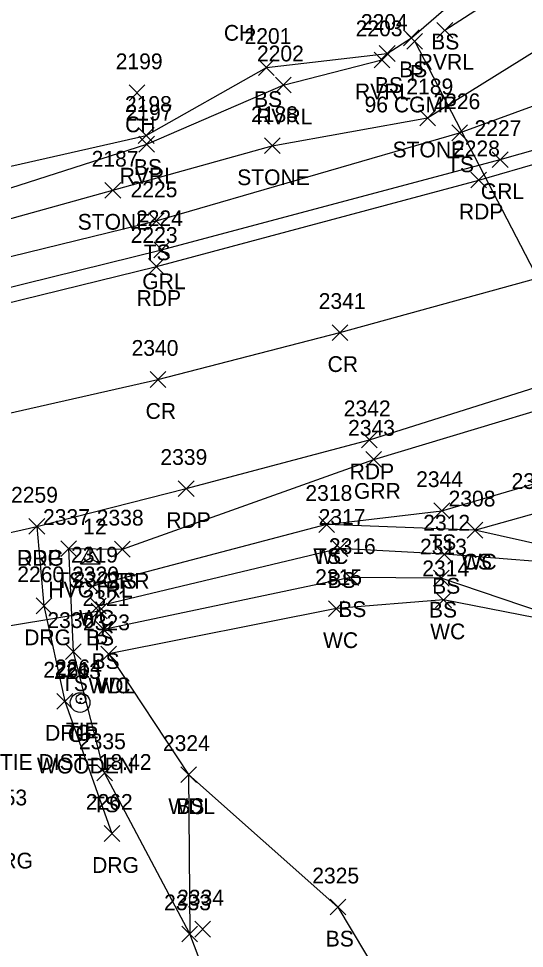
# Model space of a CAD drawing. Extents: x 1699408 to 1700423, y 840176 to 841410.
# Drawn here: x 1699855.8 to 1699920, y 840264.9 to 840382.8 of the extents above; entities that cross this region are included whole.
import ezdxf

# ---------------------------------------------------------------- set-up
doc = ezdxf.new("R2010")
doc.units = 0
for name, color, linetype in [('C_A', 7, 'Continuous'), ('C_C', 7, 'Continuous'), ('C_I', 7, 'Continuous'), ('CBP', 7, 'Continuous'), ('CPSM', 7, 'Continuous'), ('D_A', 7, 'Continuous'), ('D_C', 7, 'Continuous'), ('D_I', 7, 'Continuous'), ('D_TIC', 7, 'Continuous'), ('DCP', 7, 'Continuous'), ('L_A', 7, 'Continuous'), ('L_I', 7, 'Continuous'), ('L_TIC', 7, 'Continuous'), ('LASF', 7, 'Continuous'), ('LAWA', 7, 'Continuous'), ('LAWE', 7, 'Continuous'), ('LELB', 7, 'Continuous'), ('P_A', 7, 'Continuous'), ('P_I', 7, 'Continuous'), ('P_TIC', 7, 'Continuous'), ('PET', 7, 'Continuous'), ('PRC', 7, 'Continuous'), ('R_A', 7, 'Continuous'), ('R_C', 7, 'Continuous'), ('R_I', 7, 'Continuous'), ('R_TIC', 7, 'Continuous'), ('RDG', 7, 'Continuous'), ('RGP', 7, 'Continuous'), ('RGR', 7, 'Continuous')]:
    doc.layers.add(name, color=color, linetype=linetype)

msp = doc.modelspace()

# ---------------------------------------------------------------- linework, layer by layer
at = {"layer": 'CBP'}
for radius in [0.625, 0.0833]:
    msp.add_circle((1699863.73, 840296.5), radius, dxfattribs=at)
at = {"layer": 'CPSM'}
for p, q in [((1699863.65, 840313.64), (1699864.9, 840315.8)), ((1699866.15, 840313.64), (1699864.9, 840315.8)), ((1699864.9, 840314.36), (1699864.9, 840315.8)), ((1699863.65, 840313.64), (1699864.9, 840314.36)), ((1699864.9, 840314.36), (1699864.9, 840314.36)), ((1699864.9, 840314.36), (1699866.15, 840313.64)), ((1699863.65, 840313.64), (1699866.15, 840313.64))]:
    msp.add_line(p, q, dxfattribs=at)
at = {"layer": 'D_TIC'}
for points in [[(1699905.1, 840378.9), (1699907.1, 840380.9)], [(1699907.1, 840378.9), (1699905.1, 840380.9)], [(1699865.03, 840306.66), (1699867.03, 840308.66)], [(1699867.03, 840306.66), (1699865.03, 840308.66)]]:
    msp.add_lwpolyline(points, dxfattribs=at)
at = {"layer": 'DCP'}
for points in [[(1699906.1, 840379.9), (1699937.64, 840319.19)], [(1699838.09, 840303.05), (1699866.03, 840307.66)]]:
    msp.add_lwpolyline(points, dxfattribs=at)
at = {"layer": 'L_TIC'}
for points in [[(1699908.92, 840380.31), (1699910.92, 840382.31)], [(1699910.92, 840380.31), (1699908.92, 840382.31)], [(1699904.68, 840379.36), (1699906.68, 840381.36)], [(1699906.68, 840379.36), (1699904.68, 840381.36)], [(1699901.6, 840377.37), (1699903.6, 840379.37)], [(1699903.6, 840377.37), (1699901.6, 840379.37)], [(1699886.26, 840375.59), (1699888.26, 840377.59)], [(1699888.26, 840375.59), (1699886.26, 840377.59)], [(1699900.94, 840376.56), (1699902.94, 840378.56)], [(1699902.94, 840376.56), (1699900.94, 840378.56)], [(1699888.41, 840373.37), (1699890.41, 840375.37)], [(1699890.41, 840373.37), (1699888.41, 840375.37)], [(1699869.84, 840372.38), (1699871.84, 840374.38)], [(1699871.84, 840372.38), (1699869.84, 840374.38)], [(1699906.74, 840369.19), (1699908.74, 840371.19)], [(1699908.74, 840369.19), (1699906.74, 840371.19)], [(1699871, 840366.97), (1699873, 840368.97)], [(1699873, 840366.97), (1699871, 840368.97)], [(1699910.79, 840367.31), (1699912.79, 840369.31)], [(1699912.79, 840367.31), (1699910.79, 840369.31)], [(1699871.08, 840365.87), (1699873.08, 840367.87)], [(1699873.08, 840365.87), (1699871.08, 840367.87)], [(1699887.01, 840365.67), (1699889.01, 840367.67)], [(1699889.01, 840365.67), (1699887.01, 840367.67)], [(1699866.77, 840360.02), (1699868.77, 840362.02)], [(1699868.77, 840360.02), (1699866.77, 840362.02)], [(1699872.28, 840356.14), (1699874.28, 840358.14)], [(1699874.28, 840356.14), (1699872.28, 840358.14)], [(1699908.54, 840319.37), (1699910.54, 840321.37)], [(1699910.54, 840319.37), (1699908.54, 840321.37)], [(1699893.91, 840317.62), (1699895.91, 840319.62)], [(1699895.91, 840317.62), (1699893.91, 840319.62)], [(1699893.91, 840317.62), (1699895.91, 840319.62)], [(1699895.91, 840317.62), (1699893.91, 840319.62)], [(1699912.74, 840316.91), (1699914.74, 840318.91)], [(1699914.74, 840316.91), (1699912.74, 840318.91)], [(1699912.74, 840316.91), (1699914.74, 840318.91)], [(1699914.74, 840316.91), (1699912.74, 840318.91)], [(1699861.17, 840314.57), (1699863.17, 840316.57)], [(1699863.17, 840314.57), (1699861.17, 840316.57)], [(1699867.99, 840314.49), (1699869.99, 840316.49)], [(1699869.99, 840314.49), (1699867.99, 840316.49)], [(1699895.6, 840314.58), (1699897.6, 840316.58)], [(1699897.6, 840314.58), (1699895.6, 840316.58)], [(1699908.87, 840313.85), (1699910.87, 840315.85)], [(1699910.87, 840313.85), (1699908.87, 840315.85)], [(1699896.95, 840310.88), (1699898.95, 840312.88)], [(1699898.95, 840310.88), (1699896.95, 840312.88)], [(1699908.47, 840310.82), (1699910.47, 840312.82)], [(1699910.47, 840310.82), (1699908.47, 840312.82)], [(1699864.17, 840309.79), (1699866.17, 840311.79)], [(1699866.17, 840309.79), (1699864.17, 840311.79)], [(1699864.93, 840307.28), (1699866.93, 840309.28)], [(1699866.93, 840307.28), (1699864.93, 840309.28)], [(1699908.75, 840308.06), (1699910.75, 840310.06)], [(1699910.75, 840308.06), (1699908.75, 840310.06)], [(1699895.15, 840306.95), (1699897.15, 840308.95)], [(1699897.15, 840306.95), (1699895.15, 840308.95)], [(1699865.62, 840304.3), (1699867.62, 840306.3)], [(1699867.62, 840304.3), (1699865.62, 840306.3)], [(1699865.62, 840304.3), (1699867.62, 840306.3)], [(1699867.62, 840304.3), (1699865.62, 840306.3)], [(1699861.77, 840301.49), (1699863.77, 840303.49)], [(1699863.77, 840301.49), (1699861.77, 840303.49)], [(1699866.25, 840301.21), (1699868.25, 840303.21)], [(1699868.25, 840301.21), (1699866.25, 840303.21)], [(1699866.25, 840301.21), (1699868.25, 840303.21)], [(1699868.25, 840301.21), (1699866.25, 840303.21)], [(1699865.73, 840286.12), (1699867.73, 840288.12)], [(1699867.73, 840286.12), (1699865.73, 840288.12)], [(1699876.39, 840285.89), (1699878.39, 840287.89)], [(1699878.39, 840285.89), (1699876.39, 840287.89)], [(1699876.39, 840285.89), (1699878.39, 840287.89)], [(1699878.39, 840285.89), (1699876.39, 840287.89)], [(1699895.35, 840269.09), (1699897.35, 840271.09)], [(1699897.35, 840269.09), (1699895.35, 840271.09)], [(1699878.19, 840266.29), (1699880.19, 840268.29)], [(1699880.19, 840266.29), (1699878.19, 840268.29)], [(1699876.54, 840265.69), (1699878.54, 840267.69)], [(1699878.54, 840265.69), (1699876.54, 840267.69)], [(1699876.54, 840265.69), (1699878.54, 840267.69)], [(1699878.54, 840265.69), (1699876.54, 840267.69)], [(1699876.54, 840265.69), (1699878.54, 840267.69)], [(1699878.54, 840265.69), (1699876.54, 840267.69)]]:
    msp.add_lwpolyline(points, dxfattribs=at)
at = {"layer": 'LASF'}
msp.add_lwpolyline([(1699851.14, 840356.43), (1699867.77, 840361.02), (1699888.01, 840366.67), (1699907.74, 840370.19), (1699925.07, 840381), (1699922.64, 840389.58)], dxfattribs=at)
at = {"layer": 'LAWA'}
for points in [[(1699867.25, 840302.21), (1699877.39, 840286.89), (1699877.54, 840266.69)], [(1699884.49, 840248.38), (1699877.54, 840266.69)]]:
    msp.add_lwpolyline(points, dxfattribs=at)
at = {"layer": 'LAWE'}
for points in [[(1699909.92, 840381.31), (1699922.64, 840389.58), (1699930.57, 840394.24), (1699958.5, 840420.16), (1699988.97, 840439.06)], [(1699729.36, 840377.19), (1699755.12, 840355.85), (1699780.74, 840350.74), (1699821.29, 840354.82), (1699849, 840359.49), (1699872.08, 840366.87), (1699889.41, 840374.37), (1699901.94, 840377.56)], [(1699926.59, 840315.05), (1699913.74, 840317.91), (1699894.91, 840318.62), (1699865.17, 840310.79)], [(1699927.27, 840305.65), (1699909.75, 840309.06), (1699896.15, 840307.95), (1699867.25, 840302.21)]]:
    msp.add_lwpolyline(points, dxfattribs=at)
at = {"layer": 'LELB'}
for points in [[(1699894.91, 840318.62), (1699909.54, 840320.37), (1699931.73, 840326.89), (1699942.77, 840330.34), (1699953.04, 840332.24), (1699965.49, 840337.33), (1699971.91, 840344.73), (1700003.63, 840352.88), (1700032.87, 840363), (1700063.25, 840372.76), (1700109.93, 840390.42), (1700140.91, 840399), (1700170.04, 840412.16), (1700222.58, 840432.8), (1700261.59, 840445.7), (1700307.68, 840461.11), (1700347.68, 840474.56), (1700384.18, 840486.92), (1700414.06, 840495.99)], [(1699782.01, 840352.31), (1699821.1, 840358.64), (1699847.49, 840362.44), (1699872, 840367.97), (1699887.26, 840376.59), (1699902.6, 840378.37), (1699905.68, 840380.36), (1699909.75, 840383.88), (1699917.88, 840388.51), (1699929.29, 840395.23), (1699957.95, 840421.92), (1699988.44, 840440.99)], [(1699784.06, 840343.1), (1699812.78, 840343), (1699846.79, 840350.66), (1699873.28, 840357.14), (1699911.79, 840368.31), (1699928.14, 840374.26), (1699963.63, 840390.16), (1699976.97, 840400.87)], [(1699913.74, 840317.91), (1699921.73, 840320.13), (1699930, 840322.82), (1699931.23, 840318.59)], [(1699877.54, 840266.69), (1699866.73, 840287.12), (1699862.77, 840302.49), (1699862.17, 840315.57), (1699868.99, 840315.49)], [(1699929.07, 840313.33), (1699909.87, 840314.85), (1699896.6, 840315.58), (1699865.93, 840308.28), (1699866.62, 840305.3)], [(1699935.17, 840303.1), (1699909.47, 840311.82), (1699897.95, 840311.88), (1699866.62, 840305.3)], [(1699877.39, 840286.89), (1699896.35, 840270.09), (1699910.65, 840246.17), (1699927.62, 840231.48)]]:
    msp.add_lwpolyline(points, dxfattribs=at)
at = {"layer": 'P_TIC'}
for points in [[(1699913.22, 840361.32), (1699915.22, 840363.32)], [(1699915.22, 840361.32), (1699913.22, 840363.32)], [(1699872.3, 840350.35), (1699874.3, 840352.35)], [(1699874.3, 840350.35), (1699872.3, 840352.35)], [(1699895.6, 840341.97), (1699897.6, 840343.97)], [(1699897.6, 840341.97), (1699895.6, 840343.97)], [(1699872.5, 840336.02), (1699874.5, 840338.02)], [(1699874.5, 840336.02), (1699872.5, 840338.02)], [(1699899.35, 840328.36), (1699901.35, 840330.36)], [(1699901.35, 840328.36), (1699899.35, 840330.36)], [(1699876.08, 840322.18), (1699878.08, 840324.18)], [(1699878.08, 840322.18), (1699876.08, 840324.18)], [(1699857.12, 840317.39), (1699859.12, 840319.39)], [(1699859.12, 840317.39), (1699857.12, 840319.39)]]:
    msp.add_lwpolyline(points, dxfattribs=at)
at = {"layer": 'PET'}
for points in [[(1699430.72, 840228.22), (1699466.92, 840252.65), (1699493.58, 840268.87), (1699501.63, 840273.58), (1699505.33, 840277.49), (1699516.37, 840283.58), (1699542.26, 840294.23), (1699569.87, 840304.55), (1699598.29, 840312.45), (1699620.64, 840316.32), (1699670.9, 840322.33), (1699702.16, 840325.07), (1699741.15, 840329.16), (1699780.55, 840332.75), (1699814.05, 840338.23), (1699848.8, 840345.35), (1699873.3, 840351.35), (1699914.22, 840362.32), (1699930.57, 840367.02), (1699959.45, 840375.82), (1699990.91, 840385.72), (1700021.62, 840396.71), (1700043.81, 840403.93)], [(1699447.11, 840206.16), (1699475.63, 840224.65), (1699506.94, 840242.78), (1699536.09, 840256.08), (1699564.51, 840267.73), (1699591.88, 840277.12), (1699619.21, 840283.47), (1699647.22, 840288.99), (1699679.73, 840293.47), (1699710.33, 840296.95), (1699740.62, 840299.68), (1699772.35, 840302.79), (1699806.37, 840308.43), (1699836.08, 840313.39), (1699858.12, 840318.39), (1699877.08, 840323.18), (1699900.35, 840329.36), (1699935.97, 840340.61), (1699968.58, 840349.28), (1700000.7, 840359.42), (1700031.35, 840369.03)]]:
    msp.add_lwpolyline(points, dxfattribs=at)
at = {"layer": 'PRC'}
msp.add_lwpolyline([(1699438.11, 840217.33), (1699474.74, 840241.27), (1699500.34, 840255.97), (1699530.26, 840270.89), (1699558.33, 840282.59), (1699589.24, 840292.75), (1699616.86, 840299.45), (1699644.68, 840304.26), (1699678.81, 840308.53), (1699708.26, 840311.1), (1699739.11, 840314.27), (1699770.93, 840317.73), (1699804.23, 840322.43), (1699833.64, 840328), (1699873.5, 840337.02), (1699896.6, 840342.97), (1699933.32, 840353.07), (1699963.1, 840362.17), (1699996.81, 840372.51), (1700026.94, 840382.38)], dxfattribs=at)
at = {"layer": 'R_TIC'}
for points in [[(1699915.95, 840363.91), (1699917.95, 840365.91)], [(1699917.95, 840363.91), (1699915.95, 840365.91)], [(1699872.97, 840352.47), (1699874.97, 840354.47)], [(1699874.97, 840352.47), (1699872.97, 840354.47)], [(1699899.9, 840325.88), (1699901.9, 840327.88)], [(1699901.9, 840325.88), (1699899.9, 840327.88)], [(1699857.12, 840317.39), (1699859.12, 840319.39)], [(1699859.12, 840317.39), (1699857.12, 840319.39)], [(1699867.99, 840314.49), (1699869.99, 840316.49)], [(1699869.99, 840314.49), (1699867.99, 840316.49)], [(1699858.03, 840307.31), (1699860.03, 840309.31)], [(1699860.03, 840307.31), (1699858.03, 840309.31)], [(1699860.68, 840295.2), (1699862.68, 840297.2)], [(1699862.68, 840295.2), (1699860.68, 840297.2)], [(1699866.65, 840278.43), (1699868.65, 840280.43)], [(1699868.65, 840278.43), (1699866.65, 840280.43)]]:
    msp.add_lwpolyline(points, dxfattribs=at)
at = {"layer": 'RDG'}
msp.add_lwpolyline([(1699858.12, 840318.39), (1699859.03, 840308.31), (1699861.68, 840296.2), (1699867.65, 840279.43)], dxfattribs=at)
at = {"layer": 'RGP'}
msp.add_line((1699863.62, 840296.04), (1699863.62, 840296.04), dxfattribs=at)
for radius in [1.25, 0.0833]:
    msp.add_circle((1699863.62, 840296.04), radius, dxfattribs=at)
at = {"layer": 'RGR'}
for points in [[(1699728.48, 840335.43), (1699752.54, 840332.39), (1699780.34, 840334.41), (1699813.44, 840339.9), (1699849.41, 840347.4), (1699873.97, 840353.47), (1699916.95, 840364.91), (1699929.95, 840368.59), (1699959.73, 840377.35), (1699990.11, 840387.92), (1700008.42, 840397.8)], [(1699868.99, 840315.49), (1699900.9, 840326.88), (1699936.57, 840337.6), (1699969.35, 840346.26), (1699990.16, 840352.27), (1699998.77, 840353.73), (1700003.63, 840352.88)]]:
    msp.add_lwpolyline(points, dxfattribs=at)

# ---------------------------------------------------------------- texts
at = {"layer": 'C_A'}
for s, p in [('HVCTRL', (1699859.59, 840309.36)), ('TIE', (1699861.8, 840291.5))]:
    msp.add_text(s, height=2, dxfattribs=at).set_placement(p)
at = {"layer": 'C_C'}
msp.add_text('TIE DIST=18.42', height=2, dxfattribs=at).set_placement((1699853.43, 840287.5))
at = {"layer": 'C_I'}
for s, p in [('12', (1699864, 840317.36)), ('2264', (1699860.42, 840299.5))]:
    msp.add_text(s, height=2, dxfattribs=at).set_placement(p)
at = {"layer": 'D_A'}
for p in [(1699905.48, 840374.9), (1699865.41, 840302.66)]:
    msp.add_text('P', height=2, dxfattribs=at).set_placement(p)
at = {"layer": 'D_C'}
msp.add_text('96 CGMP', height=2, dxfattribs=at).set_placement((1699899.73, 840370.9))
at = {"layer": 'D_I'}
msp.add_text('2322', height=2, dxfattribs=at).set_placement((1699862.77, 840310.66))
at = {"layer": 'L_A'}
for s, p in [('CH', (1699881.87, 840379.99)), ('BS', (1699908.19, 840378.88)), ('RVRL', (1699906.49, 840376.31)), ('BS', (1699904.12, 840375.36)), ('BS', (1699901.04, 840373.37)), ('RVRL', (1699898.51, 840372.56)), ('BS', (1699885.7, 840371.59)), ('RVRL', (1699885.97, 840369.37)), ('CH', (1699869.33, 840368.38)), ('STONE', (1699903.28, 840365.19)), ('BS', (1699870.44, 840362.97)), ('TS', (1699910.2, 840363.31)), ('RVRL', (1699868.65, 840361.87)), ('STONE', (1699883.56, 840361.67)), ('STONE', (1699863.31, 840356.02)), ('TS', (1699871.69, 840352.14)), ('TS', (1699907.95, 840315.37)), ('WC', (1699893.22, 840313.62)), ('TS', (1699893.32, 840313.62)), ('WC', (1699912.04, 840312.91)), ('CS', (1699912.18, 840312.91)), ('TS', (1699860.58, 840310.57)), ('TS', (1699867.4, 840310.49)), ('BS', (1699895.04, 840310.58)), ('BS', (1699908.31, 840309.85)), ('BS', (1699896.39, 840306.88)), ('BS', (1699907.91, 840306.82)), ('WC', (1699863.48, 840305.79)), ('WC', (1699908.06, 840304.06)), ('BS', (1699864.37, 840303.28)), ('WC', (1699894.46, 840302.95)), ('BS', (1699865.06, 840300.3)), ('BS', (1699865.06, 840300.3)), ('TS', (1699861.18, 840297.49)), ('WDL', (1699864.67, 840297.21)), ('WC', (1699865.56, 840297.21)), ('TS', (1699865.14, 840282.12)), ('WDL', (1699874.81, 840281.89)), ('BS', (1699875.83, 840281.89)), ('BS', (1699894.8, 840265.09))]:
    msp.add_text(s, height=2, dxfattribs=at).set_placement(p)
at = {"layer": 'L_I'}
for s, p in [('2203', (1699898.6, 840380.56)), ('2204', (1699899.26, 840381.37)), ('2201', (1699884.49, 840379.59)), ('2202', (1699886.07, 840377.37)), ('2199', (1699868.14, 840376.38)), ('2189', (1699905.04, 840373.19)), ('2198', (1699869.31, 840370.97)), ('2226', (1699908.47, 840371.31)), ('2197', (1699869.39, 840369.87)), ('2188', (1699885.32, 840369.67)), ('2187', (1699865.08, 840364.02)), ('2225', (1699870.02, 840360.14)), ('2344', (1699906.28, 840323.37)), ('2309', (1699918.39, 840323.13)), ('2318', (1699892.22, 840321.62)), ('2318', (1699892.22, 840321.62)), ('2308', (1699910.4, 840320.91)), ('2308', (1699910.4, 840320.91)), ('2337', (1699858.91, 840318.57)), ('2338', (1699865.73, 840318.49)), ('2317', (1699893.9, 840318.58)), ('2312', (1699907.18, 840317.85)), ('2316', (1699895.2, 840314.88)), ('2313', (1699906.77, 840314.82)), ('2319', (1699862.47, 840313.79)), ('2314', (1699907.06, 840312.06)), ('2320', (1699862.59, 840311.28)), ('2315', (1699893.46, 840310.95)), ('2321', (1699863.92, 840308.3)), ('2321', (1699863.92, 840308.3)), ('2336', (1699859.46, 840305.49)), ('2323', (1699863.99, 840305.21)), ('2323', (1699863.99, 840305.21)), ('2335', (1699863.47, 840290.12)), ('2324', (1699874.13, 840289.89)), ('2324', (1699874.13, 840289.89)), ('2325', (1699893.09, 840273.09)), ('2333', (1699874.28, 840269.69)), ('2333', (1699874.28, 840269.69)), ('2333', (1699874.28, 840269.69)), ('2334', (1699875.93, 840270.29))]:
    msp.add_text(s, height=2, dxfattribs=at).set_placement(p)
at = {"layer": 'P_A'}
for s, p in [('RDP', (1699911.71, 840357.32)), ('RDP', (1699870.79, 840346.35)), ('CR', (1699895.04, 840337.97)), ('CR', (1699871.93, 840332.02)), ('RDP', (1699897.84, 840324.36)), ('RDP', (1699874.56, 840318.18)), ('RDP', (1699855.61, 840313.39))]:
    msp.add_text(s, height=2, dxfattribs=at).set_placement(p)
at = {"layer": 'P_I'}
for s, p in [('2228', (1699910.96, 840365.32)), ('2223', (1699870.04, 840354.35)), ('2341', (1699893.91, 840345.97)), ('2340', (1699870.15, 840340.02)), ('2342', (1699897.09, 840332.36)), ('2339', (1699873.81, 840326.18)), ('2259', (1699854.85, 840321.39))]:
    msp.add_text(s, height=2, dxfattribs=at).set_placement(p)
at = {"layer": 'R_A'}
for s, p in [('GRL', (1699914.49, 840359.91)), ('GRL', (1699871.51, 840348.47)), ('GRR', (1699898.39, 840321.88)), ('DRG', (1699855.61, 840313.39)), ('GRR', (1699866.48, 840310.49)), ('DRG', (1699856.52, 840303.31)), ('DRG', (1699859.17, 840291.2)), ('GP', (1699862.05, 840291.04)), ('DRG', (1699851.69, 840274.99)), ('DRG', (1699865.14, 840274.43))]:
    msp.add_text(s, height=2, dxfattribs=at).set_placement(p)
at = {"layer": 'R_C'}
msp.add_text('WOODEN', height=2, dxfattribs=at).set_placement((1699858.13, 840287.04))
at = {"layer": 'R_I'}
for s, p in [('2227', (1699913.69, 840367.91)), ('2224', (1699870.71, 840356.47)), ('2343', (1699897.64, 840329.88)), ('2259', (1699854.85, 840321.39)), ('2338', (1699865.73, 840318.49)), ('2260', (1699855.64, 840311.31)), ('2261', (1699858.94, 840299.2)), ('2263', (1699860.31, 840299.04)), ('2253', (1699850.94, 840282.99)), ('2262', (1699864.34, 840282.43))]:
    msp.add_text(s, height=2, dxfattribs=at).set_placement(p)

doc.saveas('drawing.dxf')
